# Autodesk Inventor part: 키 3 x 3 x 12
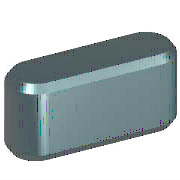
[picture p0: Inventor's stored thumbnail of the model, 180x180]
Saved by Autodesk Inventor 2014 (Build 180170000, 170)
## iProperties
Created: 2012-02
Part Number: 키 3 x 3 x 12
Material: 강철, 연강
Description: 키 및 해당 키홈
Document SubType Name: Modeling
Standard: KS B 1311
Designer: mduedu
Standards Organization: KS
Language: ko-KR
Size Designation: 3 x 3 x 12
Categories: <MemberInstance><Categories><Category DisplayName="샤프트 부품" InternalName="7f7aeb1f-a693-4053-b835-cee3144e0d98" Mnemonic="SHFT"><Category DisplayName="키" Interna
Density: 1 g/cm^3
Appearance: 강철
IsCustomPart: 1
Author: mduedu
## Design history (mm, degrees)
workplane "Work Plane1"
workplane "Work Plane2"
sketch "스케치1"
  geometry: L1 (1.5, 1.5)-(10.5, 1.5); L2 (10.5, -1.5)-(1.5, -1.5); L3 (0, 9.4)-(0, -7.4) reference; L4 (-5, 0)-(30, 0) reference; L5 (12, 0)-(12, 7); A1 r 1.5 centre (1.5, 0) between (1.5, 1.5) and (1.5, -1.5); A2 r 1.5 centre (10.5, 0) between (10.5, -1.5) and (10.5, 1.5)
  constraints: 6 end point, 5 point on circle, 4 tangent, 3 point on line, 2 centre point, 1 horizontal, 1 parallel, 1 perpendicular
  dimensions: "d0" = 1.5 radius of A1 (= 0.5 x PB); "d13" = 1.5 radius of A2 (= 0.5 x PB); "d14" = 12 distance between parallel lines of L5 L3 (= NLG)
extrude "본체1" new body sketch "스케치1" taper "d3" = 0 deg; stored distance "d4" = 10
workplane "Work Plane3"
body "Solid1"
chamfer "모따기1" distance "d8" = 0.25 (= PHH); stored, may be unused: second distance "d9" = 0.25 (= PHH), angle "d15" = 45 deg
other parameters: "d1" = -1.8 (= -PNT), "d2" = 1.2 (= PH - PNT), "NLG" = 12 [user parameter; used in 3 equation terms], "PB" = 3 [user parameter; used in 2 equation terms], "PNT" = 1.8 [user parameter; used in 2 equation terms], "PH" = 3 [user parameter; used in 1 equation term], "PHH" = 0.25 [user parameter; used in 2 equation terms], "d10" = 0, "d16" = 0, "d17" = 0, "d18" = 0, "WDMIN" = 8 [user parameter], "PLB2" = 12 (= NLG) [user parameter], "PLB1" = 12 (= NLG) [user parameter], "RR" = 0.08 [user parameter], "PUEB" = 1.4 [user parameter]
